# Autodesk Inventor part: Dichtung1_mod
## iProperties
Shininess: 64.0
Length Units: 11269
Angle Units: 11279
Time Units: 11290
Mass Units: 11283
Angle Display Precision: 1
Compacted: True
Part Number: Dichtung1_mod
Document SubType Name: Modeling
Created: 2003-04
Material: Standard
Designer: M. Sattler
Density: 0.0
Volumn: 0.0
Area: 0.0
PropertySet Name: Model Information
Control State: 0
Master: False
Checked Out: False
da: 1 mm
DN: 1 mm
Author: M. Sattler
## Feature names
1. Extrusion1
2. Extrusion2
3. Sweeping5
4. Extrusion3
5. Extrusion4
6. Sweeping4
7. Rundung1 [Fillet]
8. Extrusion5
9. Runde Anordnung1 [Circular Pattern]
10. Extrusion6
